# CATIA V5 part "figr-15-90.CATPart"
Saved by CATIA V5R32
Part number: Part1
Bounding box of the stored display mesh (mm): x -45.183 to 59.676, y -22.214 to 29.903, z -4 to 1
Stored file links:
  D:\PROJECTS\Project 2022\CATIA V5 6R 2022\Resources\Part Files\c15_catia_v5_6r2022_prt\figr-15-90.CATPart
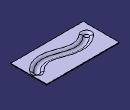
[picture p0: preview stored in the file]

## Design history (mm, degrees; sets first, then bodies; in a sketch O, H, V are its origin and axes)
SheetMetalParameters1: Thickness 1, BendRadius 5, KFactor 0.5 {= log(min(100,max(20*SheetMetalParameters1.BendRadius,SheetMetalParameters1.Thickness)/SheetMetalParameters1.Thickness))/log(100)/2}, ReliefRadialLength 1, ReliefAxialLength 2, MinimumBendRadius 0
Body1 (main body)
  Sketch1 on xy-plane, origin (0, 0, 0), H (1, 0, 0), V (0, 1, 0)
    line L1 (-45.1833, 29.903) -> (59.6761, 29.903)
    line L2 (59.6761, 29.903) -> (59.6761, -22.2137)
    line L3 (59.6761, -22.2137) -> (-45.1833, -22.2137)
    line L4 (-45.1833, -22.2137) -> (-45.1833, 29.903)
    horizontal: L1 H, L3 H
    vertical: L2 V, L4 V
  Wall1: Thickness 1, Profile Sketch1
  Sketch2 on face of Wall1, origin (0, 0, 1), H (1, 0, 0), V (0, 1, 0)
    spline S1 through (-31.3214, -3.7025) (-6.2947, 5.2247) (29.3365, -3.7025) (50.9697, 6.9251)
  d_Stamp1: Stamp_FilletRadius 4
